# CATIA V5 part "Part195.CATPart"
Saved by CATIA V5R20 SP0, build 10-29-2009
Part number: FA 168700-3
Revision: ANY
Definition: UNKNOWN
Nomenclature: FA 168700-3
Source: Unknown
Bounding box of the stored display mesh (mm): x -3 to 3, y 0 to 4.95, z -3.464 to 3.464
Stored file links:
  C:\Users\Utente\Desktop\IO LAVORO\3D X SITO CF\CUMSA\3D files FA\FA 168710-20\Part195.CATPart
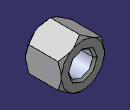
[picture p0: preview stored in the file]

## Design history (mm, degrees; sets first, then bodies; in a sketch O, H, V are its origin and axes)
Body1 "Cortar-Extruir3" (main body)
  Solid1: solid without history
